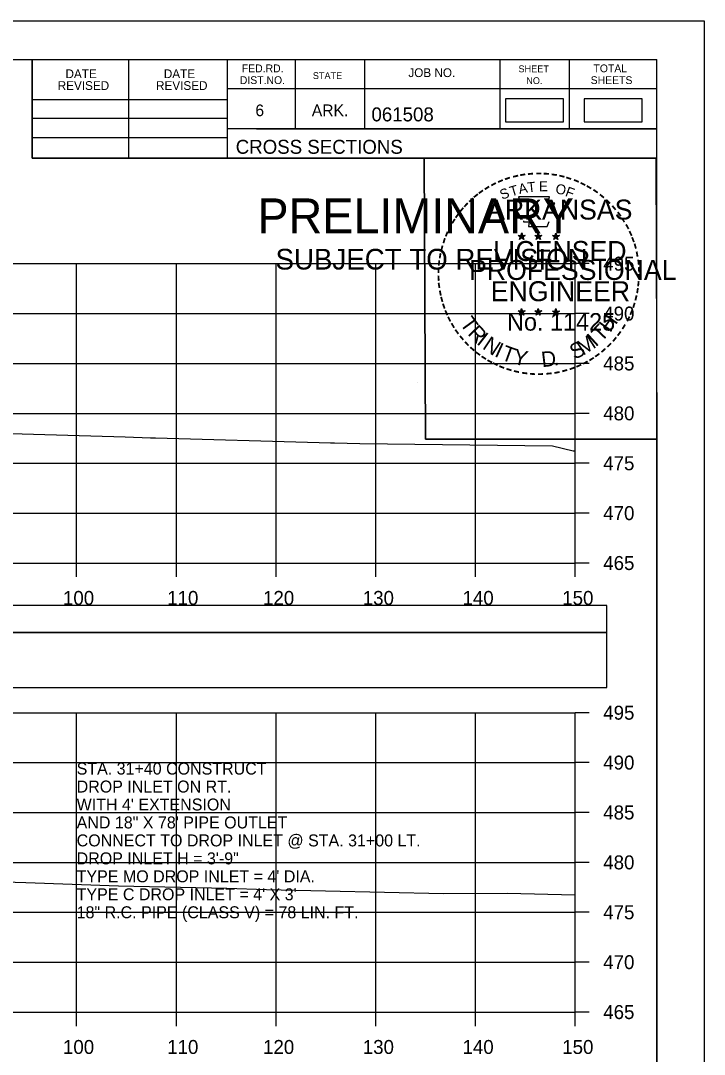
# Model space of a CAD drawing. Extents: x 1371057 to 1372761, y 380005 to 390517.
# Drawn here: x 1371655.3 to 1371723.8, y 380328.2 to 380431.8 of the extents above; entities that cross this region are included whole.
import ezdxf

# ---------------------------------------------------------------- set-up
doc = ezdxf.new("R2010")
doc.units = 0
for name, color, linetype in [('R_Axis', 7, 'Continuous'), ('R_Axis Annot', 7, 'Continuous'), ('R_Border', 7, 'Continuous'), ('R_Border PE', 7, 'Continuous'), ('R_Border Prem', 7, 'Continuous'), ('R_Detour', 7, 'Continuous'), ('R_Dimension', 7, 'Continuous'), ('R_Exist Surface', 7, 'Continuous'), ('R_Grid', 7, 'Continuous'), ('R_No Plot', 7, 'Continuous'), ('R_Water Annot', 7, 'Continuous')]:
    doc.layers.add(name, color=color, linetype=linetype)

msp = doc.modelspace()

# ---------------------------------------------------------------- linework, layer by layer
at = {"layer": 'R_Axis'}
for p, q in [((1371710.87, 380377.4), (1371710.87, 380407.4)), ((1371712.27, 380407.4), (1371710.87, 380407.4)), ((1371712.27, 380402.4), (1371710.87, 380402.4)), ((1371712.27, 380397.4), (1371710.87, 380397.4)), ((1371712.27, 380392.4), (1371710.87, 380392.4)), ((1371712.27, 380387.4), (1371710.87, 380387.4)), ((1371712.27, 380382.4), (1371710.87, 380382.4)), ((1371410.87, 380377.4), (1371710.87, 380377.4)), ((1371660.87, 380376), (1371660.87, 380377.4)), ((1371670.87, 380376), (1371670.87, 380377.4)), ((1371680.87, 380376), (1371680.87, 380377.4)), ((1371690.87, 380376), (1371690.87, 380377.4)), ((1371700.87, 380376), (1371700.87, 380377.4)), ((1371710.87, 380376), (1371710.87, 380377.4)), ((1371712.27, 380377.4), (1371710.87, 380377.4)), ((1371710.87, 380332.4), (1371710.87, 380362.4)), ((1371712.27, 380362.4), (1371710.87, 380362.4)), ((1371712.27, 380357.4), (1371710.87, 380357.4)), ((1371712.27, 380352.4), (1371710.87, 380352.4)), ((1371712.27, 380347.4), (1371710.87, 380347.4)), ((1371712.27, 380342.4), (1371710.87, 380342.4)), ((1371712.27, 380337.4), (1371710.87, 380337.4)), ((1371410.87, 380332.4), (1371710.87, 380332.4)), ((1371660.87, 380331), (1371660.87, 380332.4)), ((1371670.87, 380331), (1371670.87, 380332.4)), ((1371680.87, 380331), (1371680.87, 380332.4)), ((1371690.87, 380331), (1371690.87, 380332.4)), ((1371700.87, 380331), (1371700.87, 380332.4)), ((1371710.87, 380331), (1371710.87, 380332.4)), ((1371712.27, 380332.4), (1371710.87, 380332.4))]:
    msp.add_line(p, q, dxfattribs=at)
at = {"layer": 'R_Border'}
for p, q in [((1371402.87, 380427.86), (1371719.05, 380427.86)), ((1371656.41, 380417.98), (1371656.41, 380427.86)), ((1371666.09, 380417.98), (1371666.09, 380427.86)), ((1371675.95, 380427.86), (1371675.95, 380417.98)), ((1371682.79, 380427.86), (1371682.79, 380420.92)), ((1371689.73, 380427.86), (1371689.73, 380420.92)), ((1371703.31, 380427.86), (1371703.31, 380420.92)), ((1371710.25, 380427.86), (1371710.25, 380420.92)), ((1371719.05, 380222.4), (1371719.05, 380427.86)), ((1371719.05, 380424.92), (1371675.95, 380424.92)), ((1371719.05, 380424.94), (1371719.05, 380424.94)), ((1371656.41, 380423.84), (1371675.95, 380423.84)), ((1371656.41, 380421.98), (1371675.95, 380421.98)), ((1371719.05, 380420.92), (1371675.95, 380420.92)), ((1371678.91, 380420.92), (1371719.05, 380420.92)), ((1371656.41, 380420.04), (1371675.95, 380420.04)), ((1371719.05, 380417.98), (1371656.41, 380417.98))]:
    msp.add_line(p, q, dxfattribs=at)
at = {"layer": 'R_Border PE'}
for p, q in [((1371705.14, 380410.23), (1371705.49, 380410.12)), ((1371705.14, 380410.23), (1371705.39, 380410.19)), ((1371705.14, 380410.23), (1371705.37, 380410.11)), ((1371705.27, 380409.82), (1371705.49, 380410.12)), ((1371705.27, 380409.82), (1371705.4, 380410.07)), ((1371705.27, 380409.82), (1371705.48, 380410.04)), ((1371705.49, 380410.49), (1371705.45, 380410.23)), ((1371705.7, 380409.82), (1371705.48, 380410.04)), ((1371705.49, 380410.12), (1371705.49, 380410.49)), ((1371705.49, 380410.49), (1371705.54, 380410.24)), ((1371705.83, 380410.23), (1371705.49, 380410.12)), ((1371705.7, 380409.82), (1371705.49, 380410.12)), ((1371705.83, 380410.23), (1371705.55, 380410.18)), ((1371705.7, 380409.82), (1371705.56, 380410.12)), ((1371705.83, 380410.23), (1371705.63, 380410.13)), ((1371706.81, 380410.23), (1371707.16, 380410.12)), ((1371706.81, 380410.23), (1371707.06, 380410.19)), ((1371706.81, 380410.23), (1371707.04, 380410.11)), ((1371706.94, 380409.82), (1371707.16, 380410.12)), ((1371706.94, 380409.82), (1371707.07, 380410.07)), ((1371706.94, 380409.82), (1371707.15, 380410.04)), ((1371707.16, 380410.49), (1371707.12, 380410.23)), ((1371707.37, 380409.82), (1371707.15, 380410.04)), ((1371707.16, 380410.12), (1371707.16, 380410.49)), ((1371707.16, 380410.49), (1371707.21, 380410.24)), ((1371707.5, 380410.23), (1371707.16, 380410.12)), ((1371707.37, 380409.82), (1371707.16, 380410.12)), ((1371707.5, 380410.23), (1371707.22, 380410.18)), ((1371707.37, 380409.82), (1371707.23, 380410.12)), ((1371707.5, 380410.23), (1371707.3, 380410.13)), ((1371708.57, 380410.22), (1371708.92, 380410.11)), ((1371708.57, 380410.22), (1371708.82, 380410.18)), ((1371708.57, 380410.22), (1371708.81, 380410.1)), ((1371708.7, 380409.81), (1371708.92, 380410.11)), ((1371708.7, 380409.81), (1371708.83, 380410.06)), ((1371708.7, 380409.81), (1371708.92, 380410.03)), ((1371708.92, 380410.47), (1371708.88, 380410.22)), ((1371708.92, 380410.11), (1371708.92, 380410.47)), ((1371708.92, 380410.47), (1371708.97, 380410.22)), ((1371709.27, 380410.22), (1371708.92, 380410.11)), ((1371709.13, 380409.81), (1371708.92, 380410.11)), ((1371709.13, 380409.81), (1371708.92, 380410.03)), ((1371709.27, 380410.22), (1371708.98, 380410.17)), ((1371709.13, 380409.81), (1371709, 380410.1)), ((1371709.27, 380410.22), (1371709.06, 380410.12)), ((1371705.48, 380402.91), (1371705.44, 380402.66)), ((1371705.48, 380402.55), (1371705.48, 380402.91)), ((1371705.48, 380402.91), (1371705.53, 380402.66)), ((1371707.15, 380402.91), (1371707.11, 380402.66)), ((1371707.15, 380402.55), (1371707.15, 380402.91)), ((1371707.15, 380402.91), (1371707.2, 380402.66)), ((1371708.92, 380402.9), (1371708.88, 380402.65)), ((1371708.92, 380402.54), (1371708.92, 380402.9)), ((1371708.92, 380402.9), (1371708.97, 380402.65)), ((1371705.13, 380402.66), (1371705.48, 380402.55)), ((1371705.13, 380402.66), (1371705.39, 380402.61)), ((1371705.13, 380402.66), (1371705.37, 380402.54)), ((1371705.27, 380402.25), (1371705.48, 380402.55)), ((1371705.27, 380402.25), (1371705.39, 380402.5)), ((1371705.27, 380402.25), (1371705.48, 380402.47)), ((1371705.83, 380402.66), (1371705.48, 380402.55)), ((1371705.7, 380402.25), (1371705.48, 380402.55)), ((1371705.7, 380402.25), (1371705.48, 380402.47)), ((1371705.83, 380402.66), (1371705.54, 380402.61)), ((1371705.7, 380402.25), (1371705.56, 380402.54)), ((1371705.83, 380402.66), (1371705.63, 380402.56)), ((1371706.8, 380402.66), (1371707.15, 380402.55)), ((1371706.8, 380402.66), (1371707.06, 380402.61)), ((1371706.8, 380402.66), (1371707.04, 380402.54)), ((1371706.94, 380402.25), (1371707.15, 380402.55)), ((1371706.94, 380402.25), (1371707.06, 380402.5)), ((1371706.94, 380402.25), (1371707.15, 380402.47)), ((1371707.5, 380402.66), (1371707.15, 380402.55)), ((1371707.36, 380402.25), (1371707.15, 380402.55)), ((1371707.36, 380402.25), (1371707.15, 380402.47)), ((1371707.5, 380402.66), (1371707.21, 380402.61)), ((1371707.36, 380402.25), (1371707.23, 380402.54)), ((1371707.5, 380402.66), (1371707.29, 380402.56)), ((1371708.57, 380402.65), (1371708.92, 380402.54)), ((1371708.57, 380402.65), (1371708.82, 380402.6)), ((1371708.57, 380402.65), (1371708.81, 380402.53)), ((1371708.7, 380402.24), (1371708.92, 380402.54)), ((1371708.7, 380402.24), (1371708.83, 380402.49)), ((1371708.7, 380402.24), (1371708.92, 380402.46)), ((1371709.27, 380402.65), (1371708.92, 380402.54)), ((1371709.13, 380402.24), (1371708.92, 380402.54)), ((1371709.13, 380402.24), (1371708.92, 380402.46)), ((1371709.27, 380402.65), (1371708.98, 380402.6)), ((1371709.13, 380402.24), (1371708.99, 380402.53)), ((1371709.27, 380402.65), (1371709.06, 380402.55))]:
    msp.add_line(p, q, dxfattribs=at)
for points in [[(1371705.18, 380414.11), (1371705.45, 380413.28)], [(1371708.69, 380413.19), (1371708.83, 380413.47), (1371708.15, 380413.45), (1371708.29, 380414.11), (1371705.18, 380414.11)], [(1371705.67, 380411.69), (1371705.67, 380411.6), (1371706.23, 380411.58), (1371706.18, 380411.11), (1371708.05, 380411.11), (1371708.25, 380411.64)], [(1371705.49, 380410.49), (1371705.7, 380409.82), (1371705.14, 380410.23), (1371705.83, 380410.23), (1371705.27, 380409.82), (1371705.49, 380410.49)], [(1371707.16, 380410.49), (1371707.37, 380409.82), (1371706.81, 380410.23), (1371707.5, 380410.23), (1371706.94, 380409.82), (1371707.16, 380410.49)], [(1371708.92, 380410.47), (1371709.13, 380409.81), (1371708.57, 380410.22), (1371709.27, 380410.22), (1371708.7, 380409.81), (1371708.92, 380410.47)], [(1371705.48, 380402.91), (1371705.7, 380402.25), (1371705.13, 380402.66), (1371705.83, 380402.66), (1371705.27, 380402.25), (1371705.48, 380402.91)], [(1371707.15, 380402.91), (1371707.36, 380402.25), (1371706.8, 380402.66), (1371707.5, 380402.66), (1371706.94, 380402.25), (1371707.15, 380402.91)], [(1371708.92, 380402.9), (1371709.13, 380402.24), (1371708.57, 380402.65), (1371709.27, 380402.65), (1371708.7, 380402.24), (1371708.92, 380402.9)]]:
    msp.add_lwpolyline(points, dxfattribs=at)
for centre, radius in [((1371705.49, 380410.12), 0.172), ((1371705.49, 380410.12), 0.145), ((1371705.49, 380410.12), 0.116), ((1371705.49, 380410.12), 0.0991), ((1371705.49, 380410.12), 0.0747), ((1371705.49, 380410.12), 0.0495), ((1371705.49, 380410.12), 0.0296), ((1371707.16, 380410.12), 0.172), ((1371707.16, 380410.12), 0.145), ((1371707.16, 380410.12), 0.116), ((1371707.16, 380410.12), 0.0991), ((1371707.16, 380410.12), 0.0747), ((1371707.16, 380410.12), 0.0495), ((1371707.16, 380410.12), 0.0296), ((1371708.92, 380410.11), 0.172), ((1371708.92, 380410.11), 0.145), ((1371708.92, 380410.11), 0.116), ((1371708.92, 380410.11), 0.0991), ((1371708.92, 380410.11), 0.0747), ((1371708.92, 380410.11), 0.0495), ((1371708.92, 380410.11), 0.0296), ((1371705.48, 380402.55), 0.172), ((1371705.48, 380402.55), 0.145), ((1371707.15, 380402.55), 0.172), ((1371707.15, 380402.55), 0.145), ((1371708.92, 380402.54), 0.172), ((1371708.92, 380402.54), 0.145), ((1371705.48, 380402.55), 0.116), ((1371705.48, 380402.55), 0.0991), ((1371705.48, 380402.55), 0.0747), ((1371705.48, 380402.55), 0.0495), ((1371705.48, 380402.55), 0.0296), ((1371707.15, 380402.55), 0.116), ((1371707.15, 380402.55), 0.0991), ((1371707.15, 380402.55), 0.0747), ((1371707.15, 380402.55), 0.0495), ((1371707.15, 380402.55), 0.0296), ((1371708.92, 380402.54), 0.116), ((1371708.92, 380402.54), 0.0991), ((1371708.92, 380402.54), 0.0747), ((1371708.92, 380402.54), 0.0495), ((1371708.92, 380402.54), 0.0296)]:
    msp.add_circle(centre, radius, dxfattribs=at)
at = {"layer": 'R_Detour'}
msp.add_lwpolyline([(1371407.72, 380370.44), (1371714.03, 380370.44), (1371714.03, 380373.15), (1371407.72, 380373.15)], close=True, dxfattribs=at)
at = {"layer": 'R_Dimension'}
for points in [[(1371703.87, 380421.6), (1371709.7, 380421.6), (1371709.7, 380423.91), (1371703.87, 380423.91)], [(1371711.74, 380421.6), (1371717.57, 380421.6), (1371717.57, 380423.91), (1371711.74, 380423.91)], [(1371407.72, 380364.92), (1371714.03, 380364.92), (1371714.03, 380370.44), (1371407.72, 380370.44)]]:
    msp.add_lwpolyline(points, close=True, dxfattribs=at)
at = {"layer": 'R_Exist Surface'}
for points in [[(1371601.2, 380391.29), (1371612.44, 380391.29), (1371614.85, 380391.31), (1371617.72, 380391.33), (1371620.8, 380391.15), (1371644.35, 380390.78), (1371644.36, 380390.78), (1371644.37, 380390.78), (1371644.38, 380390.77), (1371644.55, 380390.77), (1371650.77, 380390.48), (1371665.73, 380390.05), (1371668.29, 380389.96), (1371668.76, 380389.95), (1371685.18, 380389.47), (1371686.32, 380389.44), (1371686.73, 380389.44), (1371689.26, 380389.39), (1371708.59, 380389.16), (1371710.64, 380388.64), (1371710.87, 380388.64)], [(1371603.71, 380346.39), (1371614.12, 380346.57), (1371617.05, 380346.62), (1371619.21, 380346.65), (1371626.76, 380346.42), (1371638.42, 380346), (1371644.99, 380345.73), (1371655.77, 380345.37), (1371665.06, 380345.05), (1371675.94, 380344.81), (1371679.9, 380344.69), (1371697.65, 380344.29), (1371704.04, 380344.3), (1371710.87, 380344.16)]]:
    msp.add_lwpolyline(points, dxfattribs=at)
at = {"layer": 'R_Grid'}
for p, q in [((1371410.87, 380407.4), (1371710.87, 380407.4)), ((1371660.87, 380377.4), (1371660.87, 380407.4)), ((1371670.87, 380377.4), (1371670.87, 380407.4)), ((1371680.87, 380377.4), (1371680.87, 380407.4)), ((1371690.87, 380377.4), (1371690.87, 380407.4)), ((1371700.87, 380377.4), (1371700.87, 380407.4)), ((1371710.87, 380377.4), (1371710.87, 380407.4)), ((1371410.87, 380402.4), (1371710.87, 380402.4)), ((1371410.87, 380397.4), (1371710.87, 380397.4)), ((1371410.87, 380392.4), (1371710.87, 380392.4)), ((1371410.87, 380387.4), (1371710.87, 380387.4)), ((1371410.87, 380382.4), (1371710.87, 380382.4)), ((1371410.87, 380377.4), (1371710.87, 380377.4)), ((1371410.87, 380362.4), (1371710.87, 380362.4)), ((1371660.87, 380332.4), (1371660.87, 380362.4)), ((1371670.87, 380332.4), (1371670.87, 380362.4)), ((1371680.87, 380332.4), (1371680.87, 380362.4)), ((1371690.87, 380332.4), (1371690.87, 380362.4)), ((1371700.87, 380332.4), (1371700.87, 380362.4)), ((1371710.87, 380332.4), (1371710.87, 380362.4)), ((1371410.87, 380357.4), (1371710.87, 380357.4)), ((1371410.87, 380352.4), (1371710.87, 380352.4)), ((1371410.87, 380347.4), (1371710.87, 380347.4)), ((1371410.87, 380342.4), (1371710.87, 380342.4)), ((1371410.87, 380337.4), (1371710.87, 380337.4)), ((1371410.87, 380332.4), (1371710.87, 380332.4))]:
    msp.add_line(p, q, dxfattribs=at)
at = {"layer": 'R_No Plot'}
for p, q in [((1371390.47, 380431.75), (1371723.8, 380431.75)), ((1371695.09, 380395.52), (1371695.09, 380395.52))]:
    msp.add_line(p, q, dxfattribs=at)
for points in [[(1371390.46, 380431.75), (1371723.8, 380431.75), (1371723.8, 380218.41), (1371390.46, 380218.41)], [(1371636.79, 380427.86), (1371656.41, 380427.86), (1371656.41, 380417.98), (1371672.52, 380417.98), (1371695.72, 380417.98), (1371695.84, 380389.82), (1371719.05, 380389.82), (1371719.05, 380222.4), (1371402.87, 380222.4), (1371402.87, 380427.86)], [(1371695.72, 380417.98), (1371718.93, 380417.98), (1371719.05, 380389.82), (1371695.84, 380389.82)]]:
    msp.add_lwpolyline(points, close=True, dxfattribs=at)

# ---------------------------------------------------------------- texts
at = {"layer": 'R_Axis Annot'}
for s, p in [('495', (1371713.67, 380406.7)), ('490', (1371713.67, 380401.7)), ('485', (1371713.67, 380396.7)), ('480', (1371713.67, 380391.7)), ('475', (1371713.67, 380386.7)), ('470', (1371713.67, 380381.7)), ('465', (1371713.67, 380376.7)), ('100', (1371659.5, 380373.2)), ('110', (1371669.95, 380373.2)), ('120', (1371679.56, 380373.2)), ('130', (1371689.56, 380373.2)), ('140', (1371699.56, 380373.2)), ('150', (1371709.56, 380373.2)), ('495', (1371713.67, 380361.7)), ('490', (1371713.67, 380356.7)), ('485', (1371713.67, 380351.7)), ('480', (1371713.67, 380346.7)), ('475', (1371713.67, 380341.7)), ('470', (1371713.67, 380336.7)), ('465', (1371713.67, 380331.7)), ('100', (1371659.5, 380328.2)), ('110', (1371669.95, 380328.2)), ('120', (1371679.56, 380328.2)), ('130', (1371689.56, 380328.2)), ('140', (1371699.56, 380328.2)), ('150', (1371709.56, 380328.2))]:
    msp.add_text(s, height=1.4, dxfattribs=at).set_placement(p)
at = {"layer": 'R_Border'}
for s, height, p in [('DATE', 0.879, (1371659.75, 380425.99)), ('DATE', 0.879, (1371669.61, 380425.99)), ('FED.RD.', 0.782, (1371677.43, 380426.58)), ('STATE', 0.684, (1371684.55, 380425.9)), ('JOB NO.', 0.879, (1371694.13, 380426.1)), ('SHEET', 0.684, (1371705.17, 380426.58)), ('TOTAL', 0.782, (1371712.69, 380426.58)), ('REVISED', 0.879, (1371658.97, 380424.81)), ('REVISED', 0.879, (1371668.83, 380424.81)), ('DIST.NO.', 0.782, (1371677.23, 380425.4)), ('NO.', 0.684, (1371705.95, 380425.4)), ('SHEETS', 0.782, (1371712.41, 380425.4)), ('6', 1.17, (1371678.79, 380422.18)), ('ARK.', 1.172, (1371684.45, 380422.18)), ('061508', 1.4, (1371690.43, 380421.66)), ('CROSS SECTIONS', 1.4, (1371676.82, 380418.41))]:
    msp.add_text(s, height=height, rotation=360, dxfattribs=at).set_placement(p)
at = {"layer": 'R_Border PE'}
for s, height, rotation, p in [('-', 1.6, 13.6301, (1371704.68, 380415.48)), ('-', 1.6, 10.2193, (1371705.35, 380415.64)), ('-', 1.6, 5.8968, (1371706.08, 380415.75)), ('-', 1.6, 0.1862, (1371706.86, 380415.82)), ('-', 1.6, 357.743, (1371707.58, 380415.81)), ('-', 1.6, 352.1617, (1371708.32, 380415.75)), ('-', 1.6, 347.2049, (1371709.04, 380415.64)), ('-', 1.6, 34.0636, (1371702.06, 380414.28)), ('-', 1.6, 28.7918, (1371702.66, 380414.65)), ('-', 1.6, 24.3072, (1371703.29, 380414.97)), ('-', 1.6, 19.1761, (1371703.93, 380415.24)), ('T', 1, 16.4036, (1371704.45, 380414.12)), ('A', 1, 11.2132, (1371705.27, 380414.37)), ('T', 1, 6.0228, (1371706.12, 380414.54)), ('E', 1, 0.8323, (1371707.23, 380414.65)), ('O', 1, 350.4515, (1371708.83, 380414.44)), ('F', 1, 340.0707, (1371709.79, 380414.21)), ('-', 1.6, 342.3362, (1371709.68, 380415.48)), ('-', 1.6, 337.8551, (1371710.41, 380415.26)), ('-', 1.6, 334.1211, (1371711.04, 380414.99)), ('-', 1.6, 329.6409, (1371711.62, 380414.71)), ('-', 1.6, 38.9507, (1371701.01, 380413.51)), ('-', 1.6, 36.2317, (1371701.48, 380413.89)), ('S', 1, 21.594, (1371703.53, 380413.79)), ('-', 1.6, 325.8627, (1371712.26, 380414.35)), ('-', 1.6, 320.5297, (1371712.87, 380413.92)), ('-', 1.6, 50.6142, (1371699.72, 380412.13)), ('-', 1.6, 48.423, (1371700.13, 380412.61)), ('-', 1.6, 42.9622, (1371700.58, 380413.09)), ('ARKANSAS', 2, 360, (1371702.03, 380411.82)), ('-', 1.6, 315.5786, (1371713.47, 380413.43)), ('-', 1.6, 309.8797, (1371714.04, 380412.88)), ('-', 1.6, 54.2325, (1371699.31, 380411.56)), ('-', 1.6, 306.6522, (1371714.57, 380412.28)), ('-', 1.6, 62.8713, (1371698.67, 380410.42)), ('-', 1.6, 58.0706, (1371698.99, 380411.03)), ('-', 1.4, 303.6753, (1371715.05, 380411.71)), ('-', 1.6, 299.6684, (1371715.37, 380411.11)), ('-', 1.6, 72.3945, (1371698.2, 380409.18)), ('-', 1.6, 67.7743, (1371698.41, 380409.81)), ('DWB', 0.01, 360, (1371705.47, 380410.12)), ('DWB', 0.01, 360, (1371707.14, 380410.12)), ('DWB', 0.01, 360, (1371708.91, 380410.11)), ('-', 1.6, 294.6628, (1371715.7, 380410.49)), ('-', 1.6, 290.5728, (1371715.95, 380409.92)), ('-', 1.6, 75.461, (1371698, 380408.46)), ('LICENSED', 2, 360, (1371702.63, 380407.67)), ('-', 1.6, 285.1233, (1371716.19, 380409.34)), ('-', 1.6, 81.2013, (1371697.87, 380407.75)), ('-', 1.6, 280.5493, (1371716.39, 380408.59)), ('-', 1.6, 89.0622, (1371697.77, 380406.36)), ('-', 1.6, 85.1863, (1371697.79, 380407.06)), ('PROFESSIONAL', 2, 360, (1371700.21, 380405.77)), ('-', 1.6, 276.5962, (1371716.55, 380407.83)), ('-', 1.6, 274.3301, (1371716.61, 380407.1)), ('-', 1.6, 94.1959, (1371697.8, 380405.63)), ('-', 1.6, 269.9407, (1371716.64, 380406.47)), ('-', 1.6, 98.9479, (1371697.87, 380404.97)), ('ENGINEER', 2, 360, (1371702.39, 380403.64)), ('-', 1.6, 260.9953, (1371716.55, 380405.15)), ('-', 1.6, 263.5172, (1371716.62, 380405.81)), ('-', 1.6, 101.7149, (1371698.01, 380404.23)), ('-', 1.6, 105.4578, (1371698.17, 380403.64)), ('-', 1.6, 255.7626, (1371716.44, 380404.47)), ('-', 1.6, 109.0874, (1371698.38, 380403.01)), ('-', 1.6, 114.0643, (1371698.64, 380402.41)), ('-', 1.6, 247.8887, (1371716.04, 380403.08)), ('-', 1.6, 252.8681, (1371716.26, 380403.75)), ('-', 1.6, 115.7289, (1371698.94, 380401.79)), ('T', 1.54, 306.0406, (1371699.24, 380401.39)), ('No. 11425', 1.757, 360, (1371704.02, 380400.69)), ('DWB', 0.01, 360, (1371705.47, 380402.54)), ('DWB', 0.01, 360, (1371707.14, 380402.54)), ('DWB', 0.01, 360, (1371708.91, 380402.53)), ('H', 1.54, 54.6088, (1371714.36, 380400.42)), ('-', 1.6, 244.6197, (1371715.78, 380402.45)), ('-', 1.6, 120.4471, (1371699.3, 380401.21)), ('-', 1.6, 125.8934, (1371699.7, 380400.65)), ('R', 1.54, 314.005, (1371700, 380400.34)), ('T', 1.54, 46.6444, (1371713.47, 380399.48)), ('-', 1.6, 233.8452, (1371714.98, 380401.05)), ('-', 1.6, 239.0712, (1371715.38, 380401.7)), ('-', 1.6, 130.7181, (1371700.17, 380400.1)), ('-', 1.6, 134.2238, (1371700.68, 380399.55)), ('I', 1.54, 321.9694, (1371700.9, 380399.41)), ('N', 1.54, 326.5002, (1371701.47, 380398.93)), ('S', 1.54, 26.9312, (1371710.79, 380397.75)), ('M', 1.54, 32.6563, (1371711.63, 380398.15)), ('I', 1.54, 42.1136, (1371712.91, 380399)), ('-', 1.6, 231.2538, (1371714.55, 380400.48)), ('-', 1.6, 138.9338, (1371701.21, 380399.09)), ('-', 1.6, 144.6463, (1371701.76, 380398.68)), ('I', 1.54, 335.3603, (1371702.68, 380398.15)), ('T', 1.54, 339.8912, (1371703.34, 380397.82)), ('Y', 1.54, 347.8556, (1371704.56, 380397.38)), ('D', 1.54, 6.3969, (1371707.54, 380397.02)), ('-', 1.6, 221.0851, (1371713.55, 380399.41)), ('-', 1.6, 225.7653, (1371714.07, 380399.92)), ('-', 1.6, 148.0898, (1371702.32, 380398.31)), ('-', 1.6, 151.5704, (1371702.9, 380397.98)), ('-', 1.6, 154.6002, (1371703.43, 380397.74)), ('-', 1.6, 207.3568, (1371711.91, 380398.2)), ('-', 1.6, 212.2491, (1371712.47, 380398.55)), ('-', 1.6, 215.7363, (1371713, 380398.94)), ('-', 1.6, 158.5612, (1371704.05, 380397.48)), ('-', 1.6, 162.7983, (1371704.74, 380397.27)), ('-', 1.6, 167.5555, (1371705.45, 380397.11)), ('-', 1.6, 173.1155, (1371706.22, 380397)), ('-', 1.6, 176.5183, (1371706.97, 380396.94)), ('-', 1.6, 185.8167, (1371708.52, 380397.04)), ('-', 1.6, 191.2858, (1371709.26, 380397.17)), ('.', 1.54, 13.7642, (1371708.74, 380397.15)), ('-', 1.6, 195.4743, (1371709.99, 380397.37)), ('-', 1.6, 200.7184, (1371710.67, 380397.61)), ('-', 1.6, 204.2516, (1371711.29, 380397.88)), ('-', 1.6, 181.5918, (1371707.72, 380396.96))]:
    msp.add_text(s, height=height, rotation=rotation, dxfattribs=at).set_placement(p)
at = {"layer": 'R_Border Prem'}
for s, height, p in [('PRELIMINARY', 3.5, (1371679, 380410.44)), ('DWB', 0.01, (1371679.75, 380412.29)), ('SUBJECT TO REVISION', 2.0751, (1371680.81, 380406.81))]:
    msp.add_text(s, height=height, rotation=360, dxfattribs=at).set_placement(p)
at = {"layer": 'R_Water Annot'}
for s, p in [('STA. 31+40 CONSTRUCT', (1371660.87, 380356.2)), ('DROP INLET ON RT.', (1371660.87, 380354.4)), ("WITH 4' EXTENSION", (1371660.87, 380352.6)), ('AND 18" X 78\' PIPE OUTLET', (1371660.87, 380350.8)), ('CONNECT TO DROP INLET @ STA. 31+00 LT.', (1371660.87, 380349)), ('DROP INLET H = 3\'-9"', (1371660.87, 380347.2)), ("TYPE MO DROP INLET = 4' DIA.", (1371660.87, 380345.4)), ("TYPE C DROP INLET = 4' X 3'", (1371660.87, 380343.6)), ('18" R.C. PIPE (CLASS V) = 78 LIN. FT.', (1371660.87, 380341.8))]:
    msp.add_text(s, height=1.2, dxfattribs=at).set_placement(p)

doc.saveas('drawing.dxf')
